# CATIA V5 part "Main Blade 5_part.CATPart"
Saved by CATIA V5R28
Part number: Main Blade 5_part
Definition: design
Nomenclature: Main Blade 5_part
Source: Unknown
Bounding box of the stored display mesh (mm): x -4.561 to 6.333, y 0.806 to 7.964, z 1.529 to 7.748
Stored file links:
  D:\paraturbo-cad\STEP\Turbocompressor_for_Christophe\Main Blade 5_part.CATPart
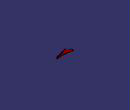
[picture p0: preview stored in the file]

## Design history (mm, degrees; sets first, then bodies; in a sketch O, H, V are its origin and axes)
Body1 "MANIFOLD_SOLID_BREP #43820" (main body)
  Solid1: solid without history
